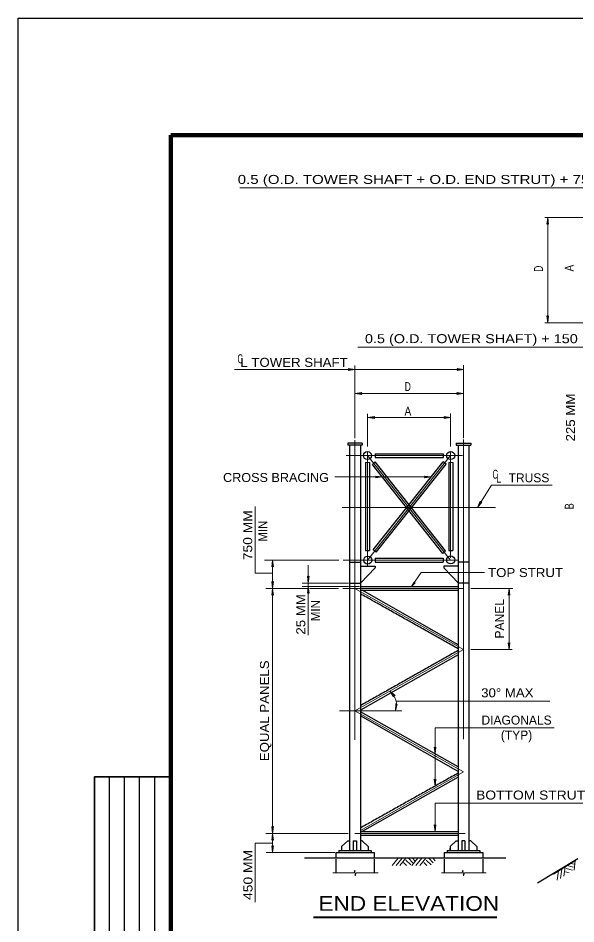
# Model space of a CAD drawing. Extents: x 312601.858 to 312602.699, y 144420.109 to 144420.704.
# Drawn here: x 312601.8578 to 312602.0439, y 144420.4014 to 144420.7035 of the extents above; entities that cross this region are included whole.
import ezdxf
from ezdxf.enums import TextEntityAlignment as Align

# ---------------------------------------------------------------- set-up
doc = ezdxf.new("R2010")
doc.units = 0
doc.header["$LTSCALE"] = 0.0012
doc.linetypes.add('DOT_DASHED', pattern=[7.7, 5, -1.2, 0.3, -1.2])
doc.linetypes.add('MEDIUM_DASHED', pattern=[4.5, 3, -1.5])
for name, color, linetype, lineweight in [('1', 7, 'Continuous', 25), ('2', 7, 'Continuous', 13), ('39', 7, 'Continuous', 13), ('60', 7, 'Continuous', 25)]:
    doc.layers.add(name, color=color, linetype=linetype, lineweight=lineweight)

msp = doc.modelspace()

# ---------------------------------------------------------------- hatches: boundary and pattern name
at = {"layer": '39'}
msp.add_hatch(color=256, dxfattribs=at).paths.add_polyline_path([(312601.99, 144420.5152), (312601.9903, 144420.5152), (312601.9891, 144420.5139), (312601.9899, 144420.5154)])

# ---------------------------------------------------------------- linework, layer by layer
at = {"layer": '1', "lineweight": 13}
for p, q in [((312601.9318, 144420.6469), (312602.0623, 144420.6469)), ((312602.0335, 144420.637), (312602.0574, 144420.637)), ((312602.0345, 144420.637), (312602.0345, 144420.6019)), ((312602.0335, 144420.6019), (312602.0574, 144420.6019)), ((312601.93, 144420.5863), (312602.0064, 144420.5863)), ((312601.9702, 144420.5876), (312601.9702, 144420.5634)), ((312602.0064, 144420.5878), (312602.0064, 144420.5634)), ((312601.9702, 144420.5783), (312602.0064, 144420.5783)), ((312601.9744, 144420.5715), (312601.9744, 144420.5606)), ((312602.0021, 144420.5716), (312602.0021, 144420.5606)), ((312601.9744, 144420.5703), (312602.0021, 144420.5703)), ((312601.9744, 144420.557), (312601.9744, 144420.5582)), ((312601.9737, 144420.5553), (312601.975, 144420.5553)), ((312602.0015, 144420.5553), (312602.0028, 144420.5553)), ((312602.0111, 144420.5403), (312602.0157, 144420.5477)), ((312602.0157, 144420.5477), (312602.036, 144420.5477)), ((312601.94, 144420.5227), (312601.9648, 144420.5227)), ((312601.9427, 144420.5227), (312601.9427, 144420.5133)), ((312601.9526, 144420.5151), (312601.968, 144420.5151)), ((312601.9526, 144420.5139), (312601.968, 144420.5139)), ((312601.9687, 144420.5139), (312601.9717, 144420.5139)), ((312602.0046, 144420.5127), (312602.0046, 144420.5139)), ((312601.9404, 144420.5133), (312601.9543, 144420.5133)), ((312601.955, 144420.5133), (312601.9647, 144420.5133)), ((312602.0088, 144420.5133), (312602.0229, 144420.5133)), ((312602.0216, 144420.5133), (312602.0216, 144420.4929)), ((312602.0226, 144420.4929), (312602.0088, 144420.4929)), ((312601.9839, 144420.4757), (312602.0352, 144420.4757)), ((312601.9858, 144420.4725), (312601.965, 144420.4725)), ((312601.9969, 144420.4668), (312602.0367, 144420.4668)), ((312601.9969, 144420.4417), (312602.0475, 144420.4417)), ((312601.9969, 144420.4417), (312601.9969, 144420.4322)), ((312602.0046, 144420.431), (312602.0046, 144420.4322)), ((312601.9404, 144420.4316), (312601.9679, 144420.4316)), ((312601.9406, 144420.4252), (312601.9635, 144420.4252)), ((312601.9826, 144420.4209), (312601.9846, 144420.4233)), ((312601.9839, 144420.4209), (312601.9859, 144420.4233)), ((312601.9852, 144420.4209), (312601.9872, 144420.4233)), ((312601.988, 144420.4233), (312601.9895, 144420.4218)), ((312601.9892, 144420.4209), (312601.9912, 144420.4233)), ((312601.9894, 144420.4233), (312601.9902, 144420.4225)), ((312601.9905, 144420.4209), (312601.9925, 144420.4233)), ((312601.9918, 144420.4209), (312601.9938, 144420.4233)), ((312601.9948, 144420.4233), (312601.9963, 144420.4218)), ((312601.9962, 144420.4233), (312601.997, 144420.4225)), ((312601.9864, 144420.4219), (312601.9874, 144420.4209)), ((312601.9872, 144420.4227), (312601.9888, 144420.4211)), ((312601.9932, 144420.4219), (312601.9942, 144420.4209)), ((312601.994, 144420.4227), (312601.9956, 144420.4211)), ((312601.9628, 144420.4185), (312601.9698, 144420.4185)), ((312601.9706, 144420.4185), (312601.9779, 144420.4185)), ((312601.9991, 144420.4185), (312602.0059, 144420.4185)), ((312602.0067, 144420.4185), (312602.014, 144420.4185))]:
    msp.add_line(p, q, dxfattribs=at)
at = {"layer": '1', "linetype": 'DOT_DASHED', "lineweight": 13}
for p, q in [((312601.9702, 144420.5628), (312601.9702, 144420.4217)), ((312602.0064, 144420.563), (312602.0064, 144420.4217)), ((312601.9744, 144420.559), (312601.9744, 144420.5207)), ((312602.0021, 144420.5588), (312602.0021, 144420.5235)), ((312601.9672, 144420.5576), (312602.0061, 144420.5576)), ((312601.9744, 144420.5576), (312602.0021, 144420.5227)), ((312601.9744, 144420.5227), (312602.0021, 144420.5576)), ((312601.9659, 144420.5403), (312602.0171, 144420.5403)), ((312601.9663, 144420.5227), (312601.9697, 144420.5227)), ((312601.9696, 144420.5227), (312602.0044, 144420.5227)), ((312601.9661, 144420.5133), (312602.0064, 144420.5133)), ((312602.0064, 144420.4929), (312601.9702, 144420.5133)), ((312602.0064, 144420.4521), (312601.972, 144420.4326)), ((312601.9702, 144420.4316), (312602.007, 144420.4316))]:
    msp.add_line(p, q, dxfattribs=at)
at = {"layer": '1'}
for p, q in [((312601.9726, 144420.5617), (312601.9678, 144420.5617)), ((312601.9678, 144420.5617), (312601.9678, 144420.5611)), ((312601.9726, 144420.5611), (312601.9678, 144420.5611)), ((312601.9684, 144420.5611), (312601.9684, 144420.4259)), ((312601.972, 144420.5611), (312601.972, 144420.4259)), ((312601.9726, 144420.5617), (312601.9726, 144420.5611)), ((312602.004, 144420.5617), (312602.0088, 144420.5617)), ((312602.004, 144420.5617), (312602.004, 144420.5611)), ((312602.004, 144420.5611), (312602.0088, 144420.5611)), ((312602.0046, 144420.5611), (312602.0046, 144420.4259)), ((312602.0082, 144420.5611), (312602.0082, 144420.4259)), ((312602.0088, 144420.5617), (312602.0088, 144420.5611)), ((312601.9769, 144420.5582), (312601.9769, 144420.557)), ((312601.9769, 144420.5582), (312601.9996, 144420.5582)), ((312601.9769, 144420.557), (312601.9996, 144420.557)), ((312601.9996, 144420.5582), (312601.9996, 144420.557)), ((312601.9737, 144420.5553), (312601.9737, 144420.5259)), ((312601.975, 144420.5553), (312601.975, 144420.5259)), ((312601.9769, 144420.5555), (312601.976, 144420.5546)), ((312601.9995, 144420.525), (312601.976, 144420.5546)), ((312601.9763, 144420.5262), (312601.9996, 144420.5555)), ((312602.0004, 144420.5258), (312601.9769, 144420.5555)), ((312601.9773, 144420.5254), (312602.0006, 144420.5547)), ((312602.0006, 144420.5547), (312601.9996, 144420.5555)), ((312602.0015, 144420.5553), (312602.0015, 144420.5259)), ((312602.0028, 144420.5553), (312602.0028, 144420.5259)), ((312601.9737, 144420.5259), (312601.975, 144420.5259)), ((312601.9773, 144420.5254), (312601.9763, 144420.5262)), ((312602.0004, 144420.5258), (312601.9995, 144420.525)), ((312602.0015, 144420.5259), (312602.0028, 144420.5259)), ((312601.9769, 144420.5234), (312601.9769, 144420.5221)), ((312601.9769, 144420.5234), (312601.9996, 144420.5234)), ((312601.9996, 144420.5234), (312601.9996, 144420.5221)), ((312601.9684, 144420.5221), (312601.972, 144420.5221)), ((312601.972, 144420.5207), (312601.9769, 144420.5207)), ((312601.972, 144420.5151), (312601.9769, 144420.5202)), ((312601.9769, 144420.5221), (312601.9996, 144420.5221)), ((312601.9769, 144420.5207), (312601.9769, 144420.5202)), ((312602.0047, 144420.5151), (312601.9998, 144420.5202)), ((312602.0083, 144420.5221), (312602.0047, 144420.5221)), ((312601.9684, 144420.5151), (312601.972, 144420.5151)), ((312601.972, 144420.5139), (312602.0046, 144420.5139)), ((312602.0083, 144420.5151), (312602.0047, 144420.5151)), ((312601.972, 144420.5127), (312602.0046, 144420.5127)), ((312602.0046, 144420.4945), (312601.9726, 144420.5127)), ((312602.0046, 144420.4912), (312601.972, 144420.4727)), ((312602.0046, 144420.4538), (312601.972, 144420.4722)), ((312602.0046, 144420.4523), (312601.972, 144420.4708)), ((312602.0046, 144420.4504), (312601.9726, 144420.4322)), ((312601.972, 144420.4322), (312602.0046, 144420.4322)), ((312601.9696, 144420.4291), (312601.9696, 144420.4259)), ((312601.9696, 144420.4291), (312601.9707, 144420.4291)), ((312601.9707, 144420.4291), (312601.9707, 144420.4259)), ((312601.972, 144420.431), (312602.0046, 144420.431)), ((312602.0069, 144420.4291), (312602.0059, 144420.4291)), ((312602.0059, 144420.4291), (312602.0059, 144420.4259)), ((312602.0069, 144420.4291), (312602.0069, 144420.4259)), ((312602.0088, 144420.4291), (312602.0082, 144420.4291)), ((312602.0109, 144420.4272), (312602.0088, 144420.4291)), ((312601.9648, 144420.4259), (312601.9756, 144420.4259)), ((312601.9648, 144420.4259), (312601.9648, 144420.4252)), ((312601.9657, 144420.4272), (312601.9657, 144420.4259)), ((312601.9746, 144420.4272), (312601.9746, 144420.4259)), ((312601.9756, 144420.4259), (312601.9756, 144420.4252)), ((312602.001, 144420.4259), (312602.0118, 144420.4259)), ((312602.001, 144420.4259), (312602.001, 144420.4252)), ((312602.002, 144420.4272), (312602.002, 144420.4259)), ((312602.002, 144420.4259), (312602.002, 144420.4267)), ((312602.0109, 144420.4272), (312602.0109, 144420.4259)), ((312602.0118, 144420.4259), (312602.0118, 144420.4252)), ((312601.9533, 144420.4235), (312602.0205, 144420.4235)), ((312601.9638, 144420.4252), (312601.9766, 144420.4252)), ((312601.9638, 144420.4252), (312601.9638, 144420.4235)), ((312601.9766, 144420.4252), (312601.9766, 144420.4235)), ((312602, 144420.4252), (312602.0128, 144420.4252)), ((312602, 144420.4252), (312602, 144420.4235)), ((312602.0128, 144420.4252), (312602.0128, 144420.4235)), ((312602.0446, 144420.4231), (312602.0311, 144420.415))]:
    msp.add_line(p, q, dxfattribs=at)
at = {"layer": '1', "linetype": 'MEDIUM_DASHED'}
for p, q in [((312601.9638, 144420.423), (312601.9638, 144420.4185)), ((312601.9766, 144420.423), (312601.9766, 144420.4185)), ((312602, 144420.423), (312602, 144420.4185)), ((312602.0128, 144420.423), (312602.0128, 144420.4185))]:
    msp.add_line(p, q, dxfattribs=at)
at = {"layer": '1', "lineweight": 13}
for points in [[(312602.0342, 144420.6348), (312602.0345, 144420.637), (312602.0348, 144420.6348), (312602.0345, 144420.635)], [(312602.0348, 144420.6042), (312602.0345, 144420.6019), (312602.0342, 144420.6042), (312602.0345, 144420.6039)], [(312601.968, 144420.5866), (312601.9702, 144420.5863), (312601.968, 144420.586), (312601.9682, 144420.5863)], [(312602.0043, 144420.5866), (312602.0065, 144420.5863), (312602.0043, 144420.586), (312602.0045, 144420.5863)], [(312601.9725, 144420.578), (312601.9702, 144420.5783), (312601.9725, 144420.5786), (312601.9722, 144420.5783)], [(312602.0042, 144420.5786), (312602.0064, 144420.5783), (312602.0042, 144420.578), (312602.0044, 144420.5783)], [(312601.9767, 144420.57), (312601.9744, 144420.5703), (312601.9767, 144420.5706), (312601.9764, 144420.5703)], [(312601.9999, 144420.5706), (312602.0021, 144420.5703), (312601.9999, 144420.57), (312602.0001, 144420.5703)], [(312601.9771, 144420.5508), (312601.9793, 144420.5505), (312601.9771, 144420.5502), (312601.9773, 144420.5505)], [(312601.9934, 144420.5508), (312601.9956, 144420.5505), (312601.9934, 144420.5502), (312601.9936, 144420.5505)], [(312602.0125, 144420.5421), (312602.0111, 144420.5403), (312602.012, 144420.5424), (312602.0122, 144420.542)], [(312601.9424, 144420.5205), (312601.9427, 144420.5227), (312601.943, 144420.5205), (312601.9427, 144420.5207)], [(312601.9549, 144420.5174), (312601.9546, 144420.5151), (312601.9543, 144420.5174), (312601.9546, 144420.5171)], [(312601.943, 144420.5156), (312601.9427, 144420.5133), (312601.9424, 144420.5156), (312601.9427, 144420.5153)], [(312601.9543, 144420.5117), (312601.9546, 144420.5139), (312601.9549, 144420.5117), (312601.9546, 144420.5119)], [(312601.9424, 144420.5111), (312601.9427, 144420.5133), (312601.943, 144420.5111), (312601.9427, 144420.5113)], [(312602.0213, 144420.5111), (312602.0216, 144420.5133), (312602.0219, 144420.5111), (312602.0216, 144420.5113)], [(312602.0219, 144420.4952), (312602.0216, 144420.4929), (312602.0213, 144420.4952), (312602.0216, 144420.4949)], [(312601.9831, 144420.4772), (312601.9818, 144420.479), (312601.9836, 144420.4776), (312601.9832, 144420.4776)], [(312601.9843, 144420.4747), (312601.9837, 144420.4725), (312601.9838, 144420.4749), (312601.9841, 144420.4745)], [(312601.9972, 144420.4604), (312601.9969, 144420.4581), (312601.9966, 144420.4604), (312601.9969, 144420.4601)], [(312601.9972, 144420.4497), (312601.9969, 144420.4474), (312601.9966, 144420.4497), (312601.9969, 144420.4494)], [(312601.943, 144420.4339), (312601.9427, 144420.4316), (312601.9424, 144420.4339), (312601.9427, 144420.4336)], [(312601.9972, 144420.4345), (312601.9969, 144420.4322), (312601.9966, 144420.4345), (312601.9969, 144420.4342)], [(312601.9424, 144420.4294), (312601.9427, 144420.4316), (312601.943, 144420.4294), (312601.9427, 144420.4296)], [(312601.943, 144420.4275), (312601.9427, 144420.4252), (312601.9424, 144420.4275), (312601.9427, 144420.4272)]]:
    msp.add_lwpolyline(points, close=True, dxfattribs=at)
for points in [[(312601.9711, 144420.5938), (312602.058, 144420.5938), (312602.0623, 144420.5938)], [(312601.9635, 144420.5505), (312601.9793, 144420.5505), (312601.9956, 144420.5505)], [(312601.9546, 144420.5211), (312601.9546, 144420.5151), (312601.9546, 144420.4977)], [(312601.9427, 144420.5133), (312601.9427, 144420.4316), (312601.9427, 144420.4252)], [(312601.9969, 144420.4668), (312601.9969, 144420.4581), (312601.9969, 144420.4474)]]:
    msp.add_lwpolyline(points, dxfattribs=at)
at = {"layer": '1'}
for points in [[(312602.0047, 144420.5207), (312601.9998, 144420.5207), (312601.9998, 144420.5202)], [(312601.9657, 144420.4272), (312601.9678, 144420.4291), (312601.9684, 144420.4291)], [(312601.9746, 144420.4272), (312601.9726, 144420.4291), (312601.972, 144420.4291)], [(312602.002, 144420.4272), (312602.004, 144420.4291), (312602.0046, 144420.4291)]]:
    msp.add_lwpolyline(points, dxfattribs=at)
at = {"layer": '1', "linetype": 'DOT_DASHED', "lineweight": 13}
msp.add_lwpolyline([(312602.0064, 144420.4521), (312601.9702, 144420.4725), (312602.0064, 144420.4929)], dxfattribs=at)
at = {"layer": '1'}
for centre in [(312601.97436, 144420.55762), (312602.00213, 144420.55762), (312601.97445, 144420.52274), (312602.00213, 144420.52282)]:
    msp.add_circle(centre, 0.00134, dxfattribs=at)
at = {"layer": '1', "lineweight": 13}
msp.add_arc((312601.97826, 144420.47446), 0.00578, 340.1549, 52.1054, dxfattribs=at)
at = {"layer": '1'}
for points in [[(312602.0046, 144420.4932), (312601.972, 144420.5115)], [(312602.0046, 144420.4926), (312601.972, 144420.4742)], [(312602.0046, 144420.4517), (312601.972, 144420.4334)]]:
    msp.add_open_spline(points, degree=1, dxfattribs=at)
at = {"layer": '2'}
for p, q in [((312601.9369, 144420.4087), (312601.9369, 144420.4284)), ((312601.9427, 144420.4284), (312601.9369, 144420.4284)), ((312602.0364, 144420.418), (312602.0438, 144420.4226)), ((312602.0399, 144420.4173), (312602.0403, 144420.4204)), ((312602.0406, 144420.4199), (312602.0428, 144420.4194)), ((312602.041, 144420.4209), (312602.0431, 144420.4204)), ((312602.0422, 144420.4216), (312602.0433, 144420.4213)), ((312602.0433, 144420.4194), (312602.0437, 144420.4225)), ((312602.0377, 144420.416), (312602.0381, 144420.4191)), ((312602.0388, 144420.4166), (312602.0392, 144420.4197)), ((312602.0404, 144420.4188), (312602.0417, 144420.4185))]:
    msp.add_line(p, q, dxfattribs=at)
at = {"layer": '2', "lineweight": 40}
msp.add_line((312601.9564, 144420.4037), (312602.0175, 144420.4037), dxfattribs=at)
at = {"layer": '2'}
for points in [[(312601.9428, 144420.5184), (312601.9369, 144420.5184), (312601.9369, 144420.5406)], [(312601.9891, 144420.5139), (312601.9923, 144420.5186), (312602.0134, 144420.5186)], [(312601.9698, 144420.4185), (312601.9701, 144420.4193), (312601.9703, 144420.4175), (312601.9706, 144420.4185)], [(312602.0059, 144420.4185), (312602.0062, 144420.4193), (312602.0064, 144420.4175), (312602.0067, 144420.4185)]]:
    msp.add_lwpolyline(points, dxfattribs=at)
at = {"layer": '39', "lineweight": 25}
for p, q in [((312601.8578, 144420.7035), (312602.6988, 144420.7035)), ((312601.8578, 144420.1095), (312601.8578, 144420.7035))]:
    msp.add_line(p, q, dxfattribs=at)
at = {"layer": '39', "lineweight": 158}
for p, q in [((312601.9088, 144420.6645), (312602.6838, 144420.6645)), ((312601.9088, 144420.1247), (312601.9088, 144420.6645))]:
    msp.add_line(p, q, dxfattribs=at)
at = {"layer": '39'}
msp.add_lwpolyline([(312601.99, 144420.5152), (312601.9903, 144420.5152), (312601.9891, 144420.5139), (312601.9899, 144420.5154)], close=True, dxfattribs=at)
at = {"layer": '60'}
for p, q in [((312601.8883, 144420.3475), (312601.8883, 144420.4505)), ((312601.8933, 144420.3475), (312601.8933, 144420.4505)), ((312601.8983, 144420.3475), (312601.8983, 144420.4505)), ((312601.9034, 144420.3475), (312601.9034, 144420.4505))]:
    msp.add_line(p, q, dxfattribs=at)
at = {"layer": '60', "lineweight": 35}
msp.add_lwpolyline([(312601.9084, 144420.3475), (312601.8833, 144420.3475), (312601.8833, 144420.4505), (312601.9084, 144420.4505)], dxfattribs=at)

# ---------------------------------------------------------------- texts
at = {"layer": '2'}
for s, height, width, p in [('0.5 (O.D. TOWER SHAFT + O.D. END STRUT) + 75 MM', 0.003, 1.25, (312601.9946, 144420.6482)), ('0.5 (O.D. TOWER SHAFT) + 150 MM', 0.003, 1.2, (312602.0137, 144420.5951)), ('L TOWER SHAFT', 0.003, 1.1, (312601.94985, 144420.5872)), ('C', 0.003, 0.6, (312602.017, 144420.5499)), ('CROSS BRACING', 0.003, 1.05, (312601.94385, 144420.5488)), ('L', 0.003, 0.75, (312602.01815, 144420.5486)), ('END ELEVATION ', 0.0049, 1.15, (312601.9892, 144420.4058))]:
    msp.add_text(s, height=height, dxfattribs=dict(at, width=width)).set_placement(p, align=Align.CENTER)
for s, width, p in [('D', 0.7, (312602.0329, 144420.6189)), ('A', 0.85, (312602.0432, 144420.619)), ('B', 0.75, (312602.0432, 144420.5397)), ('EQUAL PANELS', 1.1, (312601.9415, 144420.4557))]:
    msp.add_text(s, height=0.003, rotation=90, dxfattribs=dict(at, width=width)).set_placement(p)
for s, width, p in [('C', 0.6, (312601.931, 144420.5884)), ('D', 0.7, (312601.9868, 144420.5791)), ('A', 0.85, (312601.9867, 144420.5709)), ('TOP STRUT', 1.1, (312602.0146, 144420.5171)), ('30° MAX', 1.1, (312602.0123, 144420.477)), ('BOTTOM STRUT', 1.15, (312602.0106, 144420.4429))]:
    msp.add_text(s, height=0.003, dxfattribs=dict(at, width=width)).set_placement(p)
for s, width, p in [('225 MM', 1.1, (312602.0436, 144420.5703)), ('750 MM', 1.15, (312601.9359, 144420.53105)), ('MIN', 0.95, (312601.9409, 144420.5324)), ('25 MM', 1.1, (312601.9536, 144420.50465)), ('MIN', 0.95, (312601.9585, 144420.5059)), ('450 MM', 1.15, (312601.936, 144420.41775))]:
    msp.add_text(s, height=0.003, rotation=90, dxfattribs=dict(at, width=width)).set_placement(p, align=Align.CENTER)
for s, p in [('TRUSS', (312602.02825, 144420.5487)), ('DIAGONALS', (312602.0241, 144420.4679)), ('(TYP)', (312602.0241, 144420.4629))]:
    msp.add_text(s, height=0.003, dxfattribs=at).set_placement(p, align=Align.CENTER)
msp.add_text('PANEL', height=0.003, rotation=90, dxfattribs=at).set_placement((312602.0199, 144420.4966))

doc.saveas('drawing.dxf')
